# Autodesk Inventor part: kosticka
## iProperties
Created: 2010-03
Part Number: kosticka
Document SubType Name: Modeling
Designer: Ondra
Density: 1 g/cm^3
Author: Ondra
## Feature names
1. Extrusion1
2. Hole1
